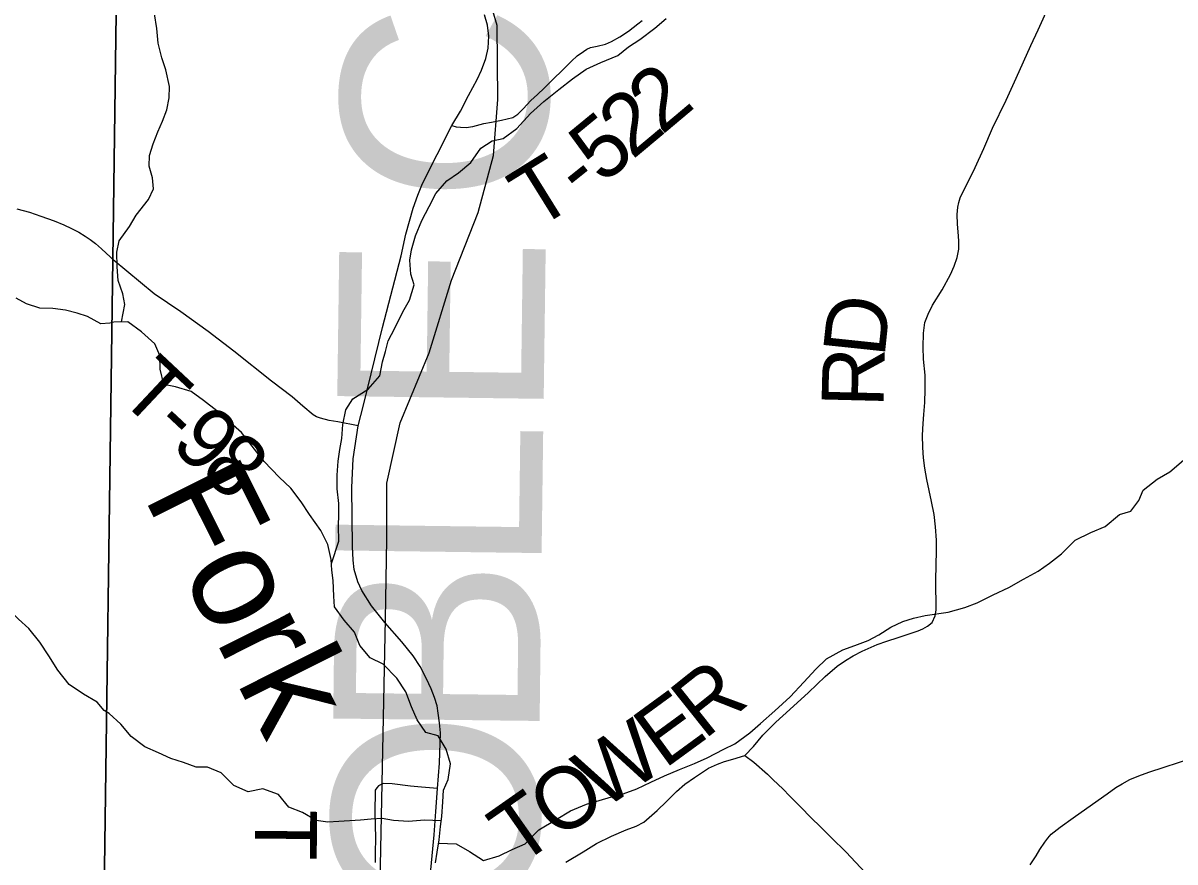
# Model space of a CAD drawing. Extents: x 0 to 34, y 0 to 22.
# Drawn here: x 5.272 to 6.329, y 15.806 to 16.577 of the extents above; entities that cross this region are included whole.
import ezdxf

# ---------------------------------------------------------------- set-up
doc = ezdxf.new("R2010")
doc.units = 0
for name, color, linetype in [('GM_X_Corporation', 7, 'Continuous'), ('GM_X_County_Road', 7, 'Continuous'), ('GM_X_County_Text', 7, 'Continuous'), ('GM_X_Minor_River', 7, 'Continuous'), ('GM_X_Minor_River_Text', 7, 'Continuous'), ('GM_X_Rail_Line', 7, 'Continuous'), ('GM_X_State_Route', 7, 'Continuous'), ('GM_X_Township_Road', 7, 'Continuous'), ('GM_X_Township_Road_Text', 7, 'Continuous')]:
    doc.layers.add(name, color=color, linetype=linetype)

msp = doc.modelspace()

# ---------------------------------------------------------------- linework, layer by layer
at = {"layer": 'GM_X_Corporation'}
for points in [[(2.9828, 15.6366), (4.3545, 15.5959), (4.7469, 15.5851), (4.7491, 15.5839), (4.752, 15.583), (4.7567, 15.5825), (4.8249, 15.5815), (4.8348, 15.5815), (4.8639, 15.5808), (4.8707, 15.5807), (4.875, 15.5807), (4.8836, 15.5806), (4.9014, 15.5802), (4.9151, 15.5796), (4.9231, 15.5793), (4.936, 15.5788), (4.9453, 15.5784), (4.9558, 15.5778), (5.3123, 15.5731), (5.3483, 15.5723), (5.3453, 15.7118), (5.3543, 16.3597), (5.3699, 17.5116)], [(5.3699, 17.5116), (5.3543, 16.3597), (5.3453, 15.7118), (5.3483, 15.5723), (5.3123, 15.5731), (4.9558, 15.5778), (4.9453, 15.5784), (4.936, 15.5788), (4.9231, 15.5793), (4.9151, 15.5796), (4.9014, 15.5802), (4.8836, 15.5806), (4.875, 15.5807), (4.8707, 15.5807), (4.8639, 15.5808), (4.8348, 15.5815), (4.8249, 15.5815), (4.7567, 15.5825), (4.752, 15.583), (4.7491, 15.5839), (4.7469, 15.5851), (4.3545, 15.5959), (2.9828, 15.6366)], [(2.9828, 15.6366), (4.3545, 15.5959), (4.7469, 15.5851), (4.7491, 15.5839), (4.752, 15.583), (4.7567, 15.5825), (4.8249, 15.5815), (4.8348, 15.5815), (4.8639, 15.5808), (4.8707, 15.5807), (4.875, 15.5807), (4.8836, 15.5806), (4.9014, 15.5802), (4.9151, 15.5796), (4.9231, 15.5793), (4.936, 15.5788), (4.9453, 15.5784), (4.9558, 15.5778), (5.3123, 15.5731), (5.3483, 15.5723), (5.3453, 15.7118), (5.3543, 16.3597), (5.3699, 17.5116)], [(5.3699, 17.5116), (5.3543, 16.3597), (5.3453, 15.7118), (5.3483, 15.5723), (5.5099, 15.5686), (5.5173, 15.5684), (5.5624, 15.5674), (5.5643, 15.5673), (5.624, 15.566), (5.6266, 15.5659), (7.0561, 15.5293), (7.0614, 15.5292), (7.2766, 15.5247), (7.2802, 15.5246), (7.2927, 15.5244), (7.5593, 15.5188), (7.5629, 15.5187), (8.3936, 15.4979)]]:
    msp.add_lwpolyline(points, dxfattribs=at)
at = {"layer": 'GM_X_County_Road'}
msp.add_lwpolyline([(5.2662, 16.406), (5.2776, 16.4028), (5.2882, 16.3994), (5.3005, 16.3949), (5.3091, 16.3914), (5.3164, 16.388), (5.323, 16.3845), (5.3289, 16.381), (5.3335, 16.3779), (5.3384, 16.3741), (5.3439, 16.3692), (5.352, 16.3615), (5.3545, 16.3592)], dxfattribs=at)
at = {"layer": 'GM_X_Minor_River'}
for points in [[(5.3622, 16.3022), (5.3652, 16.3181), (5.3633, 16.328), (5.3591, 16.3401), (5.3583, 16.3526), (5.3579, 16.3663), (5.3601, 16.3765), (5.3695, 16.3898), (5.3756, 16.4001), (5.3869, 16.4145), (5.3914, 16.4244), (5.3906, 16.4346), (5.3876, 16.4452), (5.3879, 16.4551), (5.3913, 16.4657), (5.3954, 16.4767), (5.3999, 16.4866), (5.4037, 16.4968), (5.4059, 16.5078), (5.4063, 16.5184), (5.4028, 16.5336), (5.399, 16.5446), (5.3959, 16.5582), (5.3944, 16.5715), (5.3924, 16.5851)], [(5.5548, 16.0804), (5.5616, 16.1009), (5.5612, 16.1149), (5.5615, 16.1251), (5.5615, 16.1354), (5.5599, 16.149), (5.5599, 16.1615), (5.561, 16.1744), (5.5625, 16.185), (5.5644, 16.1953), (5.5651, 16.2081), (5.5681, 16.2214), (5.5745, 16.2317), (5.5885, 16.2404), (5.599, 16.2526), (5.6016, 16.2655), (5.6043, 16.275), (5.6069, 16.2849), (5.6129, 16.2966), (5.6204, 16.3114), (5.6265, 16.3221), (5.6306, 16.3361), (5.6275, 16.346), (5.6267, 16.3589), (5.6282, 16.3683), (5.632, 16.3812), (5.6376, 16.3953), (5.6444, 16.4082), (5.6504, 16.42), (5.6606, 16.4318), (5.6712, 16.439), (5.6825, 16.4485), (5.6919, 16.4618), (5.7021, 16.4683), (5.7123, 16.4706), (5.7248, 16.4797), (5.7373, 16.4934), (5.7497, 16.5045), (5.7633, 16.5155), (5.7758, 16.5254), (5.7883, 16.5342), (5.8019, 16.5403), (5.8174, 16.5468), (5.8272, 16.5548), (5.8378, 16.5613), (5.8514, 16.5719), (5.8619, 16.5807)], [(5.3514, 16.3011), (5.3431, 16.3004), (5.3309, 16.3071), (5.3214, 16.3101), (5.3108, 16.313), (5.299, 16.3144), (5.2873, 16.3147), (5.2751, 16.3188), (5.2656, 16.324)], [(5.4621, 16.2097), (5.4496, 16.2206), (5.4374, 16.2301), (5.426, 16.2384), (5.4116, 16.2425), (5.401, 16.2447), (5.3976, 16.2587), (5.3972, 16.2713), (5.3926, 16.2822), (5.3804, 16.2932), (5.3679, 16.3022), (5.355, 16.3021), (5.3514, 16.3011)], [(5.6503, 15.8055), (5.6518, 15.8153), (5.6537, 15.8267), (5.6548, 15.8389), (5.6559, 15.8483), (5.657, 15.8616), (5.6577, 15.8722), (5.6618, 15.8821), (5.6641, 15.8965), (5.6599, 15.9101), (5.6526, 15.9222), (5.6413, 15.9252), (5.6333, 15.937), (5.6283, 15.9487), (5.623, 15.9627), (5.6146, 15.9752), (5.6021, 15.988), (5.5903, 15.9937), (5.5808, 16.005), (5.5759, 16.0175), (5.5664, 16.0285), (5.5576, 16.0406), (5.5568, 16.0504), (5.5564, 16.0648), (5.5552, 16.0743), (5.5545, 16.0842), (5.5514, 16.0978), (5.5449, 16.1107), (5.5346, 16.1254), (5.527, 16.1371), (5.5175, 16.1496), (5.5069, 16.1598), (5.4929, 16.1742), (5.4841, 16.1855), (5.4723, 16.2006), (5.4621, 16.2097)], [(5.6532, 15.8238), (5.6692, 15.823), (5.6813, 15.8162), (5.6942, 15.8079), (5.7086, 15.8121), (5.7207, 15.8179), (5.7324, 15.8232), (5.7449, 15.8358), (5.7608, 15.8453), (5.774, 15.8533), (5.7887, 15.8594), (5.8005, 15.8629), (5.8118, 15.8663), (5.8224, 15.869), (5.8349, 15.8736), (5.8477, 15.8797), (5.8602, 15.8854), (5.8742, 15.8912), (5.8878, 15.8969), (5.8996, 15.9019), (5.9147, 15.9099), (5.9249, 15.9149), (5.9385, 15.9251), (5.9483, 15.9335), (5.9615, 15.9453), (5.9755, 15.9579), (5.9883, 15.9716), (5.9993, 15.9834), (6.0091, 15.9929), (6.0238, 16.0013), (6.0348, 16.0051), (6.0473, 16.0097), (6.0571, 16.015), (6.0681, 16.0219), (6.079, 16.0272), (6.0889, 16.0303), (6.0995, 16.0326), (6.1206, 16.0357), (6.1358, 16.0399), (6.1471, 16.0442), (6.1619, 16.0518), (6.1762, 16.0583), (6.1898, 16.0659), (6.2031, 16.0735), (6.2137, 16.0808), (6.2246, 16.0892), (6.2371, 16.1017), (6.2514, 16.109), (6.2647, 16.1143), (6.2779, 16.1254), (6.2881, 16.1284), (6.2956, 16.1383), (6.2994, 16.1478), (6.3122, 16.1577), (6.324, 16.1646), (6.3364, 16.1752)], [(5.3461, 15.9455), (5.3399, 15.9531), (5.3273, 15.9606), (5.314, 15.9692), (5.3037, 15.9824), (5.2956, 15.9956), (5.2872, 16.0081), (5.2772, 16.0209), (5.2677, 16.0292), (5.2555, 16.042), (5.2418, 16.0521), (5.2288, 16.0634), (5.2181, 16.0743), (5.2059, 16.0875), (5.1967, 16.1015), (5.1848, 16.1139), (5.1749, 16.126), (5.1635, 16.1338), (5.1532, 16.1413), (5.1402, 16.1481)], [(5.6554, 15.8442), (5.64, 15.8449), (5.6256, 15.8437), (5.6116, 15.8444), (5.6014, 15.8463), (5.5911, 15.8458), (5.5813, 15.8447), (5.5616, 15.8435), (5.5514, 15.843), (5.5408, 15.8445), (5.5283, 15.8517), (5.5158, 15.8566), (5.5063, 15.8683), (5.4919, 15.8735), (5.4782, 15.8708), (5.4653, 15.8765), (5.4536, 15.8882), (5.4411, 15.8935), (5.4305, 15.8934), (5.4191, 15.8979), (5.4073, 15.9013), (5.396, 15.9066), (5.3835, 15.9122), (5.3709, 15.9217), (5.3614, 15.933), (5.3508, 15.9428), (5.3461, 15.9455)]]:
    msp.add_lwpolyline(points, dxfattribs=at)
at = {"layer": 'GM_X_Rail_Line'}
msp.add_lwpolyline([(5.5863, 14.9831), (5.5917, 15.417), (5.5983, 15.728), (5.6042, 16.0294), (5.6055, 16.1024), (5.6057, 16.1543), (5.6178, 16.2094), (5.6443, 16.2738), (5.6648, 16.3404), (5.6894, 16.4026), (5.7035, 16.455), (5.7074, 16.5065), (5.7067, 16.5743), (5.691, 16.6283)], dxfattribs=at)
at = {"layer": 'GM_X_State_Route'}
msp.add_lwpolyline([(5.6441, 15.7798), (5.6489, 15.8313), (5.6504, 15.8528), (5.6521, 15.874), (5.654, 15.8972), (5.6548, 15.9251), (5.654, 15.9342), (5.6527, 15.9431), (5.6516, 15.9497), (5.6493, 15.9573), (5.6463, 15.9655), (5.642, 15.9747), (5.6362, 15.986), (5.6296, 15.9956), (5.6193, 16.0084), (5.6037, 16.0264), (5.5916, 16.0416), (5.5826, 16.0557), (5.5789, 16.0637), (5.5757, 16.0748), (5.5746, 16.0835), (5.5741, 16.0959), (5.5734, 16.1503), (5.5748, 16.1764), (5.5792, 16.2067), (5.5841, 16.2259), (5.6017, 16.297), (5.6188, 16.3627), (5.623, 16.3828), (5.6298, 16.4066), (5.6339, 16.4185), (5.6383, 16.4294), (5.6653, 16.4825), (5.6732, 16.4956), (5.6804, 16.51), (5.6883, 16.5248), (5.6925, 16.5332), (5.6965, 16.5441), (5.6984, 16.5534), (5.6992, 16.5646), (5.698, 16.5745), (5.6952, 16.5842)], dxfattribs=at)
at = {"layer": 'GM_X_Township_Road'}
for points in [[(5.7698, 15.8064), (5.7856, 15.8156), (5.798, 15.8233), (5.8117, 15.8301), (5.8253, 15.8358), (5.8342, 15.8392), (5.8415, 15.8431), (5.8536, 15.8537), (5.8621, 15.862), (5.8712, 15.8711), (5.8789, 15.878), (5.8879, 15.8841), (5.9006, 15.8924), (5.9088, 15.8961), (5.9154, 15.8987), (5.9229, 15.9007), (5.934, 15.9041), (5.9421, 15.9125), (5.9505, 15.9228), (5.9625, 15.9349), (5.9753, 15.9465), (5.9923, 15.9619), (6.0078, 15.9766), (6.0188, 15.9861), (6.0263, 15.9915), (6.0333, 15.9957), (6.0418, 16.0001), (6.0553, 16.0061), (6.0643, 16.0092), (6.0746, 16.0124), (6.0932, 16.0185), (6.0974, 16.0205), (6.1017, 16.0228), (6.1058, 16.0263), (6.1086, 16.0324), (6.1096, 16.0376), (6.1094, 16.0653), (6.1098, 16.0922), (6.1098, 16.1018), (6.1089, 16.114), (6.1076, 16.1254), (6.1054, 16.1373), (6.1009, 16.1576), (6.0991, 16.1679), (6.098, 16.1774), (6.0972, 16.187), (6.0971, 16.1981), (6.0976, 16.2089), (6.0983, 16.2171), (6.0991, 16.2283), (6.0995, 16.24), (6.0995, 16.2534), (6.098, 16.268), (6.0976, 16.279), (6.0978, 16.2918), (6.0986, 16.2967), (6.0993, 16.3015), (6.1022, 16.3094), (6.1062, 16.3177), (6.115, 16.3317), (6.1228, 16.3457), (6.1261, 16.3535), (6.1289, 16.3612), (6.1304, 16.3689), (6.1305, 16.3767), (6.1297, 16.3849), (6.129, 16.3919), (6.1287, 16.4009), (6.1296, 16.4075), (6.1303, 16.4119), (6.1315, 16.4162), (6.1454, 16.444), (6.1532, 16.4613), (6.1614, 16.48), (6.1737, 16.5058), (6.183, 16.5259), (6.1963, 16.5558), (6.203, 16.5702), (6.2135, 16.5933)], [(5.7307, 16.4979), (5.7377, 16.5055), (5.7437, 16.5111), (5.75, 16.5167), (5.7749, 16.5415), (5.7802, 16.5463), (5.7859, 16.5505), (5.7891, 16.5525), (5.7925, 16.5541), (5.7984, 16.5554), (5.8061, 16.5573), (5.8117, 16.5595), (5.8194, 16.5639), (5.8272, 16.5691), (5.8359, 16.5759), (5.8397, 16.5789)], [(5.6653, 16.4825), (5.6693, 16.4814), (5.6733, 16.4809), (5.6785, 16.4808), (5.6845, 16.4817), (5.6946, 16.4844), (5.7015, 16.4857), (5.7107, 16.4875), (5.7212, 16.4898), (5.7259, 16.4928), (5.7307, 16.4979)], [(5.5792, 16.2067), (5.5605, 16.2104), (5.5526, 16.2118), (5.5447, 16.2138), (5.5411, 16.2151), (5.5381, 16.2169), (5.5285, 16.2248), (5.5187, 16.2334), (5.4996, 16.2477), (5.4651, 16.2753), (5.4417, 16.2934), (5.4166, 16.3115), (5.3922, 16.3281), (5.3545, 16.3592)], [(5.934, 15.9041), (5.9424, 15.8982), (5.9549, 15.8869), (5.9597, 15.8822), (5.9693, 15.8732), (5.9751, 15.8672), (5.9844, 15.8576), (5.9956, 15.8464), (6.0029, 15.8392), (6.0133, 15.829), (6.0269, 15.8154), (6.0443, 15.7969)], [(6.1957, 15.8038), (6.2014, 15.812), (6.2048, 15.8179), (6.2092, 15.8246), (6.2119, 15.8284), (6.2151, 15.8319), (6.2234, 15.8383), (6.2353, 15.8471), (6.2583, 15.8632), (6.2665, 15.8691), (6.2743, 15.8749), (6.2802, 15.8783), (6.2873, 15.882), (6.2955, 15.8854), (6.3046, 15.889), (6.346, 15.9024)], [(5.6521, 15.874), (5.6373, 15.8752), (5.6273, 15.8761), (5.6104, 15.8782), (5.6022, 15.8785), (5.5997, 15.8773), (5.5979, 15.8762), (5.5963, 15.8744), (5.5948, 15.8722), (5.5947, 15.8511), (5.5951, 15.8287), (5.595, 15.8146), (5.5948, 15.8061)]]:
    msp.add_lwpolyline(points, dxfattribs=at)

# ---------------------------------------------------------------- texts
at = {"layer": 'GM_X_County_Text'}
for s, rotation, p in [('C', 89.2288, (5.7519, 16.4099)), ('E', 89.2311, (5.7492, 16.2108)), ('L', 89.2485, (5.7473, 16.0692)), ('B', 89.3168, (5.7455, 15.9151)), ('O', 89.5387, (5.7441, 15.7478))]:
    msp.add_text(s, height=0.1894, rotation=rotation, dxfattribs=at).set_placement(p)
at = {"layer": 'GM_X_Minor_River_Text'}
msp.add_text('Fork', height=0.09469, rotation=296.6104, dxfattribs=at).set_placement((5.3817, 16.1426))
at = {"layer": 'GM_X_Township_Road_Text'}
for s, rotation, p in [('2', 40.0855, (5.8577, 16.4731)), ('2', 39.9316, (5.8307, 16.4505)), ('5', 39.4328, (5.8033, 16.4279)), ('T', 31.87, (5.7423, 16.3861)), ('-', 38.7111, (5.7845, 16.4128)), ('D', 83.9784, (6.0621, 16.2689)), ('T', 316.8003, (5.3575, 16.2336)), ('R', 88.5792, (6.0611, 16.2234)), ('-', 316.877, (5.3886, 16.2044)), ('9', 317.2092, (5.4059, 16.1882)), ('8', 318.6621, (5.4327, 16.1634)), ('R', 38.5467, (5.8966, 15.918)), ('E', 36.1723, (5.8603, 15.8913)), ('W', 33.4408, (5.8029, 15.8533)), ('O', 33.1909, (5.7608, 15.8258)), ('T', 34.9941, (5.7264, 15.8017)), ('T', 269.5586, (5.4848, 15.8546))]:
    msp.add_text(s, height=0.0568, rotation=rotation, dxfattribs=at).set_placement(p)

doc.saveas('drawing.dxf')
